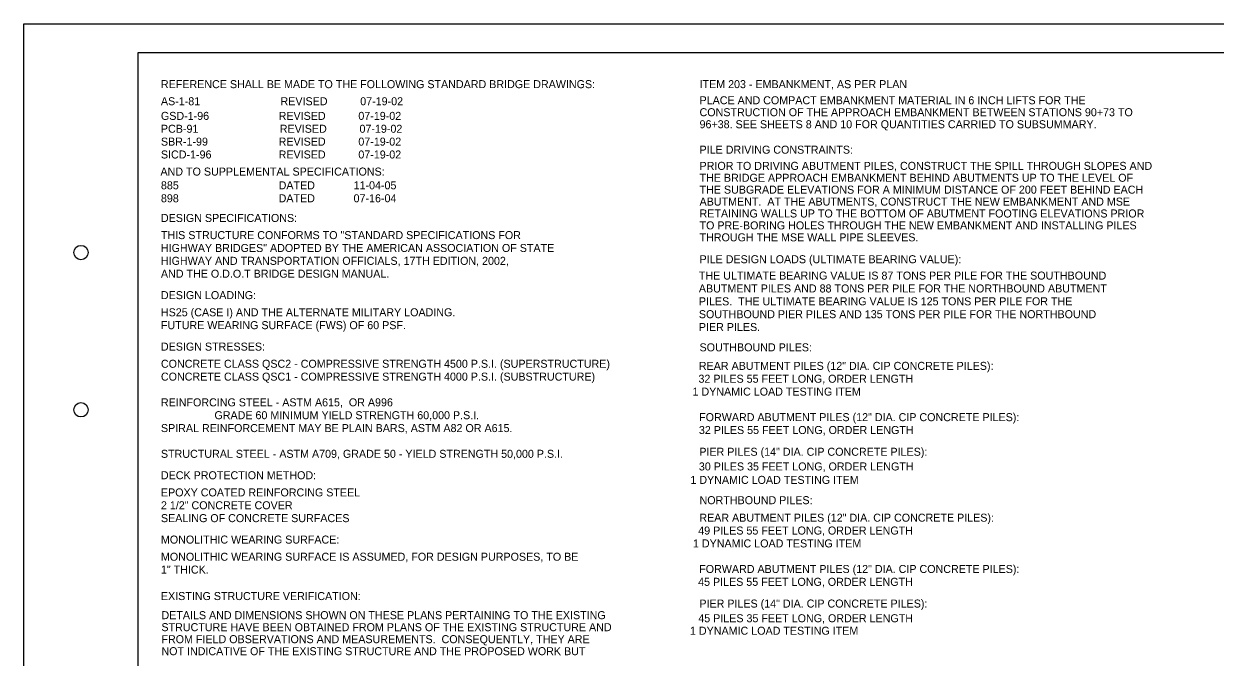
# Model space of a CAD drawing. Extents: x 0 to 34, y 0 to 22.
# Drawn here: x 0 to 20.84, y 10.92 to 22 of the extents above; entities that cross this region are included whole.
import ezdxf

# ---------------------------------------------------------------- set-up
doc = ezdxf.new("R2010")
doc.units = 0
for name, color, linetype in [('SH_Border', 7, 'Continuous'), ('SH_Cut_Line', 7, 'Continuous'), ('SH_Text', 7, 'Continuous')]:
    doc.layers.add(name, color=color, linetype=linetype)

msp = doc.modelspace()

# ---------------------------------------------------------------- linework, layer by layer
at = {"layer": 'SH_Border'}
msp.add_lwpolyline([(2, 21.5), (33.5, 21.5), (33.5, 0.5), (2, 0.5)], close=True, dxfattribs=at)
for centre in [(1, 18), (1, 15.25)]:
    msp.add_circle(centre, 0.125, dxfattribs=at)
at = {"layer": 'SH_Cut_Line'}
msp.add_lwpolyline([(0, 22), (34, 22), (34, 0), (0, 0)], close=True, dxfattribs=at)

# ---------------------------------------------------------------- texts
at = {"layer": 'SH_Text'}
for s, p in [('REFERENCE SHALL BE MADE TO THE FOLLOWING STANDARD BRIDGE DRAWINGS:', (2.398, 20.875)), ('ITEM 203 - EMBANKMENT, AS PER PLAN', (11.819, 20.875)), ('AS-1-81', (2.398, 20.576)), ('REVISED           07-19-02', (4.49, 20.576)), ('PLACE AND COMPACT EMBANKMENT MATERIAL IN 6 INCH LIFTS FOR THE', (11.819, 20.593)), ('GSD-1-96  ', (2.398, 20.32)), ('REVISED           07-19-02', (4.457, 20.32)), ('CONSTRUCTION OF THE APPROACH EMBANKMENT BETWEEN STATIONS 90+73 TO', (11.819, 20.384)), ('PCB-91', (2.398, 20.095)), ('REVISED           07-19-02', (4.477, 20.095)), ('96+38. SEE SHEETS 8 AND 10 FOR QUANTITIES CARRIED TO SUBSUMMARY. ', (11.819, 20.174)), ('SBR-1-99 ', (2.398, 19.87)), ('REVISED           07-19-02', (4.457, 19.87)), ('PILE DRIVING CONSTRAINTS:', (11.819, 19.729)), ('SICD-1-96 ', (2.398, 19.645)), ('REVISED           07-19-02', (4.457, 19.645)), ('PRIOR TO DRIVING ABUTMENT PILES, CONSTRUCT THE SPILL THROUGH SLOPES AND', (11.819, 19.446)), ('AND TO SUPPLEMENTAL SPECIFICATIONS:', (2.39, 19.346)), ('THE BRIDGE APPROACH EMBANKMENT BEHIND ABUTMENTS UP TO THE LEVEL OF', (11.819, 19.238)), ('885', (2.398, 19.106)), ('DATED             11-04-05', (4.457, 19.106)), ('THE SUBGRADE ELEVATIONS FOR A MINIMUM DISTANCE OF 200 FEET BEHIND EACH', (11.819, 19.03)), ('898', (2.398, 18.879)), ('DATED             07-16-04', (4.457, 18.879)), ('ABUTMENT.  AT THE ABUTMENTS, CONSTRUCT THE NEW EMBANKMENT AND MSE ', (11.819, 18.821)), ('RETAINING WALLS UP TO THE BOTTOM OF ABUTMENT FOOTING ELEVATIONS PRIOR', (11.819, 18.613)), ('DESIGN SPECIFICATIONS:', (2.398, 18.535)), ('TO PRE-BORING HOLES THROUGH THE NEW EMBANKMENT AND INSTALLING PILES', (11.819, 18.405)), ('THIS STRUCTURE CONFORMS TO "STANDARD SPECIFICATIONS FOR', (2.398, 18.235)), ('THROUGH THE MSE WALL PIPE SLEEVES.  ', (11.819, 18.196)), ('HIGHWAY BRIDGES" ADOPTED BY THE AMERICAN ASSOCIATION OF STATE', (2.398, 18.01)), ('HIGHWAY AND TRANSPORTATION OFFICIALS, 17TH EDITION, 2002, ', (2.398, 17.785)), ('PILE DESIGN LOADS (ULTIMATE BEARING VALUE):', (11.819, 17.813)), ('AND THE O.D.O.T BRIDGE DESIGN MANUAL.', (2.398, 17.56)), ('THE ULTIMATE BEARING VALUE IS 87 TONS PER PILE FOR THE SOUTHBOUND', (11.807, 17.527)), ('DESIGN LOADING:', (2.398, 17.185)), ('ABUTMENT PILES AND 88 TONS PER PILE FOR THE NORTHBOUND ABUTMENT', (11.807, 17.302)), ('PILES.  THE ULTIMATE BEARING VALUE IS 125 TONS PER PILE FOR THE', (11.807, 17.077)), ('HS25 (CASE I) AND THE ALTERNATE MILITARY LOADING.', (2.398, 16.885)), ('SOUTHBOUND PIER PILES AND 135 TONS PER PILE FOR THE NORTHBOUND ', (11.807, 16.852)), ('FUTURE WEARING SURFACE (FWS) OF 60 PSF.', (2.398, 16.66)), ('PIER PILES.', (11.807, 16.627)), ('DESIGN STRESSES:', (2.398, 16.285)), ('SOUTHBOUND PILES:', (11.819, 16.272)), ('CONCRETE CLASS QSC2 - COMPRESSIVE STRENGTH 4500 P.S.I. (SUPERSTRUCTURE)', (2.398, 15.985)), ('REAR ABUTMENT PILES (12" DIA. CIP CONCRETE PILES):', (11.807, 15.948)), ('CONCRETE CLASS QSC1 - COMPRESSIVE STRENGTH 4000 P.S.I. (SUBSTRUCTURE)', (2.398, 15.76)), ('32 PILES 55 FEET LONG, ORDER LENGTH', (11.8, 15.723)), ('  1 DYNAMIC LOAD TESTING ITEM', (11.592, 15.498)), ('REINFORCING STEEL - ASTM A615,  OR A996', (2.398, 15.31)), ('                  GRADE 60 MINIMUM YIELD STRENGTH 60,000 P.S.I.', (2.398, 15.085)), ('FORWARD ABUTMENT PILES (12" DIA. CIP CONCRETE PILES):', (11.812, 15.051)), ('SPIRAL REINFORCEMENT MAY BE PLAIN BARS, ASTM A82 OR A615.', (2.398, 14.86)), ('32 PILES 55 FEET LONG, ORDER LENGTH', (11.808, 14.826)), ('PIER PILES (14" DIA. CIP CONCRETE PILES):', (11.815, 14.446)), ('STRUCTURAL STEEL - ASTM A709, GRADE 50 - YIELD STRENGTH 50,000 P.S.I.', (2.398, 14.41)), ('DECK PROTECTION METHOD:', (2.398, 14.035)), ('30 PILES 35 FEET LONG, ORDER LENGTH', (11.807, 14.189)), ('   1 DYNAMIC LOAD TESTING ITEM', (11.503, 13.954)), ('EPOXY COATED REINFORCING STEEL', (2.398, 13.735)), ('2 1/2" CONCRETE COVER', (2.398, 13.51)), ('NORTHBOUND PILES:', (11.819, 13.599)), ('SEALING OF CONCRETE SURFACES', (2.398, 13.285)), ('REAR ABUTMENT PILES (12" DIA. CIP CONCRETE PILES):', (11.815, 13.293)), ('49 PILES 55 FEET LONG, ORDER LENGTH', (11.796, 13.068)), ('MONOLITHIC WEARING SURFACE:', (2.398, 12.91)), ('  1 DYNAMIC LOAD TESTING ITEM', (11.6, 12.843)), ('MONOLITHIC WEARING SURFACE IS ASSUMED, FOR DESIGN PURPOSES, TO BE', (2.398, 12.61)), ('1" THICK.', (2.398, 12.385)), ('FORWARD ABUTMENT PILES (12" DIA. CIP CONCRETE PILES):', (11.813, 12.396)), ('45 PILES 55 FEET LONG, ORDER LENGTH', (11.794, 12.171)), ('EXISTING STRUCTURE VERIFICATION:', (2.398, 11.922)), ('PIER PILES (14" DIA. CIP CONCRETE PILES):', (11.816, 11.791)), ('DETAILS AND DIMENSIONS SHOWN ON THESE PLANS PERTAINING TO THE EXISTING', (2.407, 11.588)), ('45 PILES 35 FEET LONG, ORDER LENGTH', (11.797, 11.534)), ('STRUCTURE HAVE BEEN OBTAINED FROM PLANS OF THE EXISTING STRUCTURE AND', (2.407, 11.378)), ('FROM FIELD OBSERVATIONS AND MEASUREMENTS.  CONSEQUENTLY, THEY ARE ', (2.407, 11.168)), ('   1 DYNAMIC LOAD TESTING ITEM', (11.496, 11.316)), ('NOT INDICATIVE OF THE EXISTING STRUCTURE AND THE PROPOSED WORK BUT ', (2.407, 10.958))]:
    msp.add_text(s, height=0.14, dxfattribs=at).set_placement(p)

doc.saveas('drawing.dxf')
